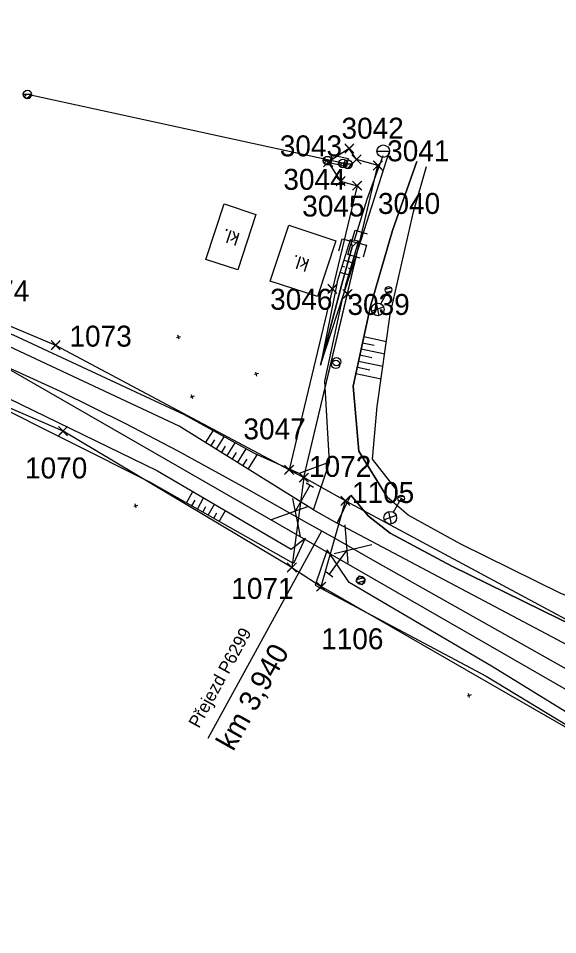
# Model space of a CAD drawing. Extents: x -738085 to -734426, y -1122197 to -1119748.
# Drawn here: x -737079.5 to -737015.1, y -1121533.3 to -1121424 of the extents above; entities that cross this region are included whole.
import ezdxf

# ---------------------------------------------------------------- set-up
doc = ezdxf.new("R2010")
doc.units = 0
for name, color, linetype in [('Dočasný zábor - do 1 roku', 7, 'Continuous'), ('SŽDC', 7, 'Continuous'), ('Trvalý zábor', 7, 'Continuous'), ('VBř', 7, 'Continuous'), ('Vrstva 1', 7, 'Continuous'), ('Vrstva 11', 7, 'Continuous'), ('Vrstva 12', 7, 'Continuous'), ('Vrstva 13', 7, 'Continuous'), ('Vrstva 23', 7, 'Continuous'), ('Vrstva 25', 7, 'Continuous'), ('Vrstva 4', 7, 'Continuous'), ('Vrstva 41', 7, 'Continuous'), ('Vrstva 43', 7, 'Continuous'), ('Vrstva 47', 7, 'Continuous'), ('Vrstva 48', 7, 'Continuous'), ('Vrstva 49', 7, 'Continuous'), ('Vrstva 51', 7, 'Continuous'), ('Vrstva 60', 7, 'Continuous'), ('Vrstva 63', 7, 'Continuous')]:
    doc.layers.add(name, color=color, linetype=linetype)

msp = doc.modelspace()

# ---------------------------------------------------------------- linework, layer by layer
at = {"layer": 'Dočasný zábor - do 1 roku'}
msp.add_lwpolyline([(-737045.41, -1121478.75), (-737036.56, -1121441.5), (-737039.12, -1121440.79), (-737039.98, -1121439.48), (-737042.49, -1121441.12), (-737041.01, -1121443.39), (-737039.05, -1121443.92), (-737047.17, -1121477.81)], dxfattribs=at)
at = {"layer": 'SŽDC'}
for p, q in [((-737045.41, -1121478.75), (-737046.85, -1121489.48)), ((-737043.34, -1121491.76), (-737040.45, -1121481.52)), ((-737040.45, -1121481.52), (-737004.89, -1121500.61)), ((-737010.34, -1121510.73), (-737043.34, -1121491.76))]:
    msp.add_line(p, q, dxfattribs=at)
for points in [[(-737087.62, -1121457.67), (-737075.04, -1121462.94), (-737045.41, -1121478.75)], [(-737046.85, -1121489.48), (-737074.16, -1121473.2), (-737092.92, -1121465.1)]]:
    msp.add_lwpolyline(points, dxfattribs=at)
at = {"layer": 'Trvalý zábor'}
for p, q in [((-737045.41, -1121478.75), (-737046.85, -1121489.48)), ((-737040.45, -1121481.52), (-737045.41, -1121478.75)), ((-737043.34, -1121491.76), (-737040.45, -1121481.52)), ((-737046.85, -1121489.48), (-737043.34, -1121491.76))]:
    msp.add_line(p, q, dxfattribs=at)
at = {"layer": 'VBř'}
for p, q in [((-737041.01, -1121443.39), (-737039.05, -1121443.92)), ((-737047.17, -1121477.81), (-737045.41, -1121478.75)), ((-737045.41, -1121478.75), (-737045.86, -1121478.3)), ((-737045.86, -1121478.3), (-737045.41, -1121478.75))]:
    msp.add_line(p, q, dxfattribs=at)
for points in [[(-737045.41, -1121478.75), (-737036.56, -1121441.5), (-737039.12, -1121440.79), (-737039.98, -1121439.48), (-737042.49, -1121441.12), (-737041.01, -1121443.39), (-737039.05, -1121443.92), (-737047.17, -1121477.81)], [(-737039.98, -1121439.48), (-737042.49, -1121441.12), (-737041.01, -1121443.39)], [(-737036.56, -1121441.5), (-737039.12, -1121440.79), (-737039.98, -1121439.48)], [(-737045.41, -1121478.75), (-737040.2, -1121456.84), (-737036.56, -1121441.5)], [(-737039.05, -1121443.92), (-737042, -1121456.22), (-737047.17, -1121477.81)]]:
    msp.add_lwpolyline(points, dxfattribs=at)
at = {"layer": 'Vrstva 1'}
msp.add_lwpolyline([(-736980.55, -1121520.47), (-736994.79, -1121512.43), (-737006.13, -1121506.04), (-737037.15, -1121488.58), (-737041.66, -1121486.03), (-737045.03, -1121484.13), (-737051.95, -1121480.26), (-737060.41, -1121475.6), (-737066.65, -1121472.32), (-737074.48, -1121468.48), (-737081.82, -1121465.13)], dxfattribs=at)
msp.add_lwpolyline([(-736980.55, -1121520.47), (-736994.79, -1121512.43), (-737006.13, -1121506.04), (-737037.15, -1121488.58), (-737041.66, -1121486.03), (-737045.03, -1121484.13), (-737051.95, -1121480.26), (-737060.41, -1121475.6), (-737066.65, -1121472.32), (-737074.48, -1121468.48), (-737081.82, -1121465.13)], dxfattribs=at)
at = {"layer": 'Vrstva 11'}
for p, q in [((-737077.91, -1121433.02), (-737078.92, -1121433.02)), ((-737078.81, -1121433.32), (-737078.51, -1121433.02)), ((-737078.48, -1121433.52), (-737077.98, -1121433.02)), ((-737042.08, -1121440.92), (-737043.09, -1121440.92)), ((-737042.98, -1121441.22), (-737042.68, -1121440.92)), ((-737042.65, -1121441.41), (-737042.15, -1121440.92)), ((-737040.25, -1121441.25), (-737041.25, -1121441.25)), ((-737041.15, -1121441.55), (-737040.84, -1121441.25)), ((-737040.81, -1121441.74), (-737040.32, -1121441.25)), ((-737039.64, -1121441.35), (-737040.65, -1121441.35)), ((-737040.54, -1121441.66), (-737040.24, -1121441.35)), ((-737040.2, -1121441.85), (-737039.71, -1121441.35)), ((-737038.22, -1121490.71), (-737039.11, -1121490.96)), ((-737038.12, -1121491.07), (-737039, -1121491.32))]:
    msp.add_line(p, q, dxfattribs=at)
for centre, radius in [((-737078.41, -1121433.02), 0.503), ((-737042.59, -1121440.92), 0.503), ((-737040.75, -1121441.25), 0.503), ((-737040.14, -1121441.35), 0.503), ((-737038.61, -1121491.01), 0.5)]:
    msp.add_circle(centre, radius, dxfattribs=at)
for centre in [(-737078.41, -1121433.02), (-737042.59, -1121440.92), (-737040.75, -1121441.25), (-737040.14, -1121441.35)]:
    msp.add_arc(centre, 0.503, 180, 0, dxfattribs=at)
at = {"layer": 'Vrstva 12'}
msp.add_line((-737038.46, -1121491.55), (-737039.16, -1121491.16), dxfattribs=at)
for points in [[(-737038.77, -1121490.46), (-737038.07, -1121490.86), (-737038.46, -1121491.55), (-737039.16, -1121491.16), (-737038.77, -1121490.46)], [(-737039.16, -1121491.16), (-737039.16, -1121491.16), (-737038.77, -1121490.46)], [(-737038.46, -1121491.55), (-737038.46, -1121491.55), (-737038.07, -1121490.86)]]:
    msp.add_lwpolyline(points, dxfattribs=at)
at = {"layer": 'Vrstva 13'}
for points in [[(-737039.35, -1121450.42), (-737037.86, -1121445.51), (-737035.95, -1121440.32)], [(-737043.43, -1121465.32), (-737040.86, -1121455.66), (-737039.63, -1121451.23)]]:
    msp.add_lwpolyline(points, dxfattribs=at)
at = {"layer": 'Vrstva 23'}
for points in [[(-737053.29, -1121453.97), (-737057.09, -1121452.72), (-737054.9, -1121446.09)], [(-737054.9, -1121446.09), (-737051.12, -1121447.34), (-737053.29, -1121453.97)], [(-737043.79, -1121457.14), (-737049.41, -1121455.3), (-737047.19, -1121448.63)], [(-737047.19, -1121448.63), (-737041.6, -1121450.48), (-737043.79, -1121457.14)]]:
    msp.add_lwpolyline(points, dxfattribs=at)
at = {"layer": 'Vrstva 25'}
for p, q in [((-737040.75, -1121441.25), (-737078.41, -1121433.02)), ((-737035, -1121456.1), (-737035.68, -1121456.29)), ((-737034.91, -1121456.49), (-737035.55, -1121456.67)), ((-737036.22, -1121458.02), (-737035.49, -1121456.71)), ((-737035.89, -1121458.41), (-737037.29, -1121458.91)), ((-737036.43, -1121459.4), (-737036.75, -1121457.95)), ((-737034.72, -1121482.89), (-737033.99, -1121481.59)), ((-737033.5, -1121480.97), (-737034.18, -1121481.16)), ((-737033.41, -1121481.36), (-737034.05, -1121481.54)), ((-737034.94, -1121484.27), (-737035.26, -1121482.82)), ((-737034.39, -1121483.28), (-737035.8, -1121483.77))]:
    msp.add_line(p, q, dxfattribs=at)
msp.add_lwpolyline([(-737042.28, -1121441.22), (-737042.08, -1121440.25), (-737040.12, -1121440.66), (-737040.32, -1121441.63), (-737042.28, -1121441.22)], dxfattribs=at)
for centre, radius in [((-737035.29, -1121456.36), 0.4), ((-737036.58, -1121458.68), 0.749), ((-737033.79, -1121481.24), 0.4), ((-737035.09, -1121483.54), 0.749)]:
    msp.add_circle(centre, radius, dxfattribs=at)
at = {"layer": 'Vrstva 4'}
for p, q in [((-737044.26, -1121479.92), (-737045.13, -1121479.43)), ((-737044.69, -1121479.68), (-737046.4, -1121482.73)), ((-737045.81, -1121485.76), (-737046.71, -1121481.24)), ((-737044.97, -1121482.22), (-737049.3, -1121483.8)), ((-737041.66, -1121486.03), (-737045.03, -1121484.13)), ((-737040.5, -1121484.38), (-737040.15, -1121488.97)), ((-737043.28, -1121485.12), (-737056.88, -1121509.88)), ((-737041.77, -1121487.79), (-737037.28, -1121486.74)), ((-737042.35, -1121490.28), (-737040.28, -1121487.45)), ((-737042.75, -1121489.98), (-737041.95, -1121490.57))]:
    msp.add_line(p, q, dxfattribs=at)
at = {"layer": 'Vrstva 41'}
msp.add_line((-737036.68, -1121439.8), (-737035.17, -1121439.8), dxfattribs=at)
msp.add_circle((-737035.93, -1121439.8), 0.752, dxfattribs=at)
at = {"layer": 'Vrstva 43'}
for points in [[(-737038.7, -1121452.55), (-737040.14, -1121452.12), (-737039.26, -1121449.24), (-737037.83, -1121449.68)], [(-737041.21, -1121451.71), (-737040.84, -1121450.26), (-737037.93, -1121451), (-737038.31, -1121452.45)]]:
    msp.add_lwpolyline(points, dxfattribs=at)
at = {"layer": 'Vrstva 47'}
for centre in [(-737041.6, -1121465.25), (-737041.5, -1121464.92)]:
    msp.add_circle(centre, 0.5, dxfattribs=at)
at = {"layer": 'Vrstva 48'}
for p, q in [((-737040.6, -1121452.82), (-737040.11, -1121452.97)), ((-737039.64, -1121453.11), (-737040.11, -1121452.97)), ((-737041.05, -1121454.25), (-737040.51, -1121454.42)), ((-737040.83, -1121453.53), (-737040.57, -1121453.61)), ((-737039.86, -1121453.83), (-737040.09, -1121453.76)), ((-737040.07, -1121454.55), (-737040.51, -1121454.42)), ((-737038.24, -1121461.92), (-737035.53, -1121462.5)), ((-737038.39, -1121462.65), (-737037.02, -1121462.94)), ((-737038.71, -1121464.11), (-737037.28, -1121464.42)), ((-737038.55, -1121463.38), (-737035.74, -1121463.98)), ((-737038.87, -1121464.85), (-737035.96, -1121465.47)), ((-737039.18, -1121466.31), (-737036.17, -1121466.96)), ((-737039.02, -1121465.58), (-737037.54, -1121465.9)), ((-737057.14, -1121474.59), (-737056.24, -1121473.15)), ((-737055.86, -1121475.39), (-737054.93, -1121473.88)), ((-737056.5, -1121474.99), (-737056.04, -1121474.25)), ((-737055.22, -1121475.78), (-737054.75, -1121475.01)), ((-737054.59, -1121476.18), (-737053.61, -1121474.6)), ((-737053.95, -1121476.57), (-737053.45, -1121475.77)), ((-737053.31, -1121476.97), (-737052.3, -1121475.33)), ((-737052.04, -1121477.76), (-737050.96, -1121476.03)), ((-737052.68, -1121477.36), (-737052.16, -1121476.53)), ((-737059.43, -1121481.76), (-737058.66, -1121480.4)), ((-737058.78, -1121482.13), (-737058.4, -1121481.46)), ((-737058.12, -1121482.5), (-737057.37, -1121481.16)), ((-737057.47, -1121482.87), (-737057.09, -1121482.2)), ((-737056.82, -1121483.24), (-737056.07, -1121481.92)), ((-737055.51, -1121483.97), (-737054.78, -1121482.68)), ((-737056.16, -1121483.6), (-737055.79, -1121482.95))]:
    msp.add_line(p, q, dxfattribs=at)
at = {"layer": 'Vrstva 49'}
for p, q in [((-737041.42, -1121455.44), (-737039.83, -1121450.33)), ((-737060.15, -1121461.94), (-737060.62, -1121462.08)), ((-737060.31, -1121462.25), (-737060.46, -1121461.77)), ((-737050.83, -1121466.32), (-737051.31, -1121466.46)), ((-737051, -1121466.63), (-737051.14, -1121466.15)), ((-737058.51, -1121469.05), (-737058.99, -1121469.2)), ((-737058.68, -1121469.36), (-737058.83, -1121468.89)), ((-737044.27, -1121482.58), (-737042.34, -1121476.89)), ((-737065.24, -1121482.06), (-737065.72, -1121482.21)), ((-737065.41, -1121482.37), (-737065.56, -1121481.89)), ((-737025.44, -1121504.68), (-737025.92, -1121504.82)), ((-737025.61, -1121504.99), (-737025.74, -1121504.51))]:
    msp.add_line(p, q, dxfattribs=at)
for points in [[(-737042.34, -1121476.89), (-737045.96, -1121478.25), (-737051.31, -1121475.87), (-737059.65, -1121471.27), (-737080.08, -1121461.77), (-737095, -1121456.37), (-737113.75, -1121449.99), (-737130.88, -1121445.35), (-737152.07, -1121440.92), (-737182.74, -1121436.67), (-737232.31, -1121430.11), (-737263.17, -1121426.36), (-737285.47, -1121423.95)], [(-737310.42, -1121426.45), (-737286.42, -1121429.49), (-737275.45, -1121430.82), (-737274.62, -1121430.93), (-737264.2, -1121432.22), (-737232.43, -1121436.47), (-737211.46, -1121439.21), (-737210.67, -1121439.32), (-737183.93, -1121442.81), (-737153.07, -1121447.16), (-737152.28, -1121447.28), (-737151.31, -1121447.32), (-737132.33, -1121451.66), (-737115.31, -1121456.24), (-737098.74, -1121461.42), (-737083.52, -1121467.94), (-737082.8, -1121468.28), (-737082.23, -1121468.54), (-737062.89, -1121477.93), (-737046.92, -1121487.27), (-737045.25, -1121485.97)], [(-737044.27, -1121482.58), (-737060.3, -1121472.63), (-737080.61, -1121463.09), (-737095.26, -1121457.2), (-737114.01, -1121450.88), (-737131.11, -1121446.1), (-737152.37, -1121441.79), (-737182.77, -1121437.5), (-737232.42, -1121431.25), (-737263.17, -1121426.36)], [(-737045.25, -1121485.97), (-737046.65, -1121488.98), (-737063.8, -1121479.29), (-737083.11, -1121469.63), (-737099.88, -1121463.72), (-737115.42, -1121458.07), (-737133.05, -1121454.14), (-737151.03, -1121450.6), (-737184.2, -1121445.28), (-737232.18, -1121438.43), (-737264.79, -1121434.28), (-737286.45, -1121430.89), (-737310.61, -1121428.1)], [(-737035.47, -1121481.1), (-737038.83, -1121475.61), (-737039.5, -1121467.82), (-737037.46, -1121458.31), (-737034.84, -1121449.28), (-737031.92, -1121441.02)], [(-737034.31, -1121480.25), (-737037.19, -1121476.55), (-737036.64, -1121470.28), (-737035.08, -1121459.3), (-737032.33, -1121447.03), (-737030.76, -1121441.64)], [(-737039.83, -1121450.33), (-737038.87, -1121450.51), (-737040.44, -1121455.79), (-737040.72, -1121457.06)], [(-737039.83, -1121450.33), (-737039.63, -1121451.23), (-737038.87, -1121450.51)], [(-737039.63, -1121451.23), (-737040.86, -1121455.66), (-737043.43, -1121465.32)], [(-737041.42, -1121455.44), (-737043.43, -1121465.32), (-737040.72, -1121457.06)], [(-736973.99, -1121521.88), (-736994.43, -1121510.5), (-737003.21, -1121504.6), (-737002.95, -1121504.16), (-737004.19, -1121503.37), (-737003.45, -1121502.97), (-737004.09, -1121501.98), (-737004.75, -1121503.06), (-737006.15, -1121502.28), (-737006.39, -1121502.71), (-737041.44, -1121484.19), (-737039.81, -1121480.83)], [(-736973.99, -1121521.88), (-736980.68, -1121514.64), (-736992.59, -1121507.66), (-737004.74, -1121500.51), (-737014.86, -1121495.64), (-737027.74, -1121489.3), (-737035.09, -1121485.37), (-737037.67, -1121483.34), (-737039.81, -1121480.83)], [(-737042.62, -1121487.38), (-737044.06, -1121491.58), (-737023.65, -1121502.44), (-737009.08, -1121511.25), (-736996.15, -1121517.06), (-736967.08, -1121533.28)], [(-737007.85, -1121508.5), (-737010.39, -1121509.02), (-737023.01, -1121501.24), (-737040, -1121491.28), (-737042.62, -1121487.38)]]:
    msp.add_lwpolyline(points, dxfattribs=at)
at = {"layer": 'Vrstva 51'}
msp.add_line((-737044.27, -1121482.58), (-737042.34, -1121476.89), dxfattribs=at)
for points in [[(-737042.34, -1121476.89), (-737042.89, -1121467.25), (-737040.72, -1121457.06), (-737037.89, -1121448.28), (-737035.22, -1121439.92)], [(-737031.92, -1121441.02), (-737034.84, -1121449.28), (-737037.46, -1121458.31), (-737039.5, -1121467.82), (-737038.83, -1121475.61), (-737035.47, -1121481.1)], [(-737044.27, -1121482.58), (-737041.44, -1121484.19), (-737039.81, -1121480.83)], [(-737039.81, -1121480.83), (-737037.67, -1121483.34), (-737035.09, -1121485.37), (-737027.74, -1121489.3), (-737014.86, -1121495.64), (-737004.74, -1121500.51), (-736999.04, -1121501.76)], [(-736998.8, -1121498.01), (-737003.34, -1121497.1), (-737014.74, -1121492.59), (-737026.65, -1121486.68), (-737032.95, -1121483.22), (-737035.47, -1121481.1)]]:
    msp.add_lwpolyline(points, dxfattribs=at)
at = {"layer": 'Vrstva 60'}
for p, q in [((-737039.53, -1121439.93), (-737040.53, -1121438.93)), ((-737039.53, -1121439.03), (-737040.53, -1121440.03)), ((-737040.43, -1121439.93), (-737039.43, -1121438.93)), ((-737040.43, -1121439.03), (-737039.43, -1121440.03)), ((-737039.98, -1121439.48), (-737039.98, -1121439.48)), ((-737042.04, -1121441.57), (-737043.04, -1121440.57)), ((-737042.04, -1121440.67), (-737043.04, -1121441.67)), ((-737042.94, -1121441.57), (-737041.94, -1121440.57)), ((-737042.94, -1121440.67), (-737041.94, -1121441.67)), ((-737042.49, -1121441.12), (-737042.49, -1121441.12)), ((-737038.67, -1121441.24), (-737039.67, -1121440.24)), ((-737038.67, -1121440.34), (-737039.67, -1121441.34)), ((-737039.57, -1121441.24), (-737038.57, -1121440.24)), ((-737039.57, -1121440.34), (-737038.57, -1121441.34)), ((-737039.12, -1121440.79), (-737039.12, -1121440.79)), ((-737036.11, -1121441.95), (-737037.11, -1121440.95)), ((-737036.11, -1121441.05), (-737037.11, -1121442.05)), ((-737037.01, -1121441.95), (-737036.01, -1121440.95)), ((-737037.01, -1121441.05), (-737036.01, -1121442.05)), ((-737036.56, -1121441.5), (-737036.56, -1121441.5)), ((-737040.56, -1121443.84), (-737041.56, -1121442.84)), ((-737040.56, -1121442.94), (-737041.56, -1121443.94)), ((-737041.46, -1121443.84), (-737040.46, -1121442.84)), ((-737041.46, -1121442.94), (-737040.46, -1121443.94)), ((-737041.01, -1121443.39), (-737041.01, -1121443.39)), ((-737038.6, -1121444.37), (-737039.6, -1121443.37)), ((-737039.5, -1121444.37), (-737038.5, -1121443.37)), ((-737038.6, -1121443.47), (-737039.6, -1121444.47)), ((-737039.5, -1121443.47), (-737038.5, -1121444.47)), ((-737039.05, -1121443.92), (-737039.05, -1121443.92)), ((-737041.55, -1121456.67), (-737042.55, -1121455.67)), ((-737041.55, -1121455.77), (-737042.55, -1121456.77)), ((-737042.45, -1121456.67), (-737041.45, -1121455.67)), ((-737042.45, -1121455.77), (-737041.45, -1121456.77)), ((-737042, -1121456.22), (-737042, -1121456.22)), ((-737039.75, -1121457.29), (-737040.75, -1121456.29)), ((-737039.75, -1121456.39), (-737040.75, -1121457.39)), ((-737040.65, -1121457.29), (-737039.65, -1121456.29)), ((-737040.65, -1121456.39), (-737039.65, -1121457.39)), ((-737040.2, -1121456.84), (-737040.2, -1121456.84)), ((-737074.59, -1121463.39), (-737075.59, -1121462.39)), ((-737074.59, -1121462.49), (-737075.59, -1121463.49)), ((-737075.49, -1121463.39), (-737074.49, -1121462.39)), ((-737075.49, -1121462.49), (-737074.49, -1121463.49)), ((-737075.04, -1121462.94), (-737075.04, -1121462.94)), ((-737073.71, -1121473.65), (-737074.71, -1121472.65)), ((-737073.71, -1121472.75), (-737074.71, -1121473.75)), ((-737074.61, -1121473.65), (-737073.61, -1121472.65)), ((-737074.61, -1121472.75), (-737073.61, -1121473.75)), ((-737074.16, -1121473.2), (-737074.16, -1121473.2)), ((-737046.72, -1121478.26), (-737047.72, -1121477.26)), ((-737046.72, -1121477.36), (-737047.72, -1121478.36)), ((-737047.62, -1121478.26), (-737046.62, -1121477.26)), ((-737047.62, -1121477.36), (-737046.62, -1121478.36)), ((-737047.17, -1121477.81), (-737047.17, -1121477.81)), ((-737044.96, -1121479.2), (-737045.96, -1121478.2)), ((-737044.96, -1121478.3), (-737045.96, -1121479.3)), ((-737045.86, -1121479.2), (-737044.86, -1121478.2)), ((-737045.86, -1121478.3), (-737044.86, -1121479.3)), ((-737045.41, -1121478.75), (-737045.41, -1121478.75)), ((-737040, -1121481.97), (-737041, -1121480.97)), ((-737040, -1121481.07), (-737041, -1121482.07)), ((-737040.9, -1121481.97), (-737039.9, -1121480.97)), ((-737040.9, -1121481.07), (-737039.9, -1121482.07)), ((-737040.45, -1121481.52), (-737040.45, -1121481.52)), ((-737046.4, -1121489.93), (-737047.4, -1121488.93)), ((-737046.4, -1121489.03), (-737047.4, -1121490.03)), ((-737047.3, -1121489.93), (-737046.3, -1121488.93)), ((-737047.3, -1121489.03), (-737046.3, -1121490.03)), ((-737046.85, -1121489.48), (-737046.85, -1121489.48)), ((-737042.89, -1121492.21), (-737043.89, -1121491.21)), ((-737042.89, -1121491.31), (-737043.89, -1121492.31)), ((-737043.79, -1121492.21), (-737042.79, -1121491.21)), ((-737043.79, -1121491.31), (-737042.79, -1121492.31)), ((-737043.34, -1121491.76), (-737043.34, -1121491.76))]:
    msp.add_line(p, q, dxfattribs=at)
at = {"layer": 'Vrstva 63'}
msp.add_line((-737099.21, -1121455.15), (-736981.97, -1121522.48), dxfattribs=at)

# ---------------------------------------------------------------- texts
at = {"layer": 'Vrstva 23'}
for rotation, p in [(161.8665, (-737052.95, -1121449.63)), (161.8316, (-737044.64, -1121452.74))]:
    msp.add_text('kl.', height=1.5, rotation=rotation, dxfattribs=at).set_placement(p)
at = {"layer": 'Vrstva 4'}
for s, height, rotation, p in [('Přejezd P6299', 1.5, 61.2107, (-737057.94, -1121508.74)), ('km 3,940', 2.5, 60.5679, (-737053.84, -1121511.5))]:
    msp.add_text(s, height=height, rotation=rotation, dxfattribs=at).set_placement(p)
at = {"layer": 'Vrstva 60'}
for s, p in [('3042', (-737040.91, -1121438.31)), ('3043', (-737048.28, -1121440.42)), ('3041', (-737035.46, -1121441.01)), ('3044', (-737047.85, -1121444.41)), ('3045', (-737045.6, -1121447.6)), ('3040', (-737036.56, -1121447.29)), ('1074', (-737085.62, -1121457.72)), ('3046', (-737049.43, -1121458.72)), ('3039', (-737040.2, -1121459.34)), ('1073', (-737073.39, -1121463.12)), ('3047', (-737052.62, -1121474.19)), ('1072', (-737044.79, -1121478.66)), ('1070', (-737078.7, -1121478.85)), ('1105', (-737039.66, -1121481.78)), ('1071', (-737054.07, -1121493.22)), ('1106', (-737043.34, -1121499.23))]:
    msp.add_text(s, height=2.5, dxfattribs=at).set_placement(p)

doc.saveas('drawing.dxf')
